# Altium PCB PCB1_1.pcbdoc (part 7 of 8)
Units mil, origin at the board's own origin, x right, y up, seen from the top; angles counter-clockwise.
Board outline 3937.01 x 3346.46 mil, 6 copper layers (Top Layer, Signal-1, SIG, POWER, Signal-4, Bottom Layer), stack 60.565 mil thick; 256 components, 201 nets, 1360 pads, 815 vias.
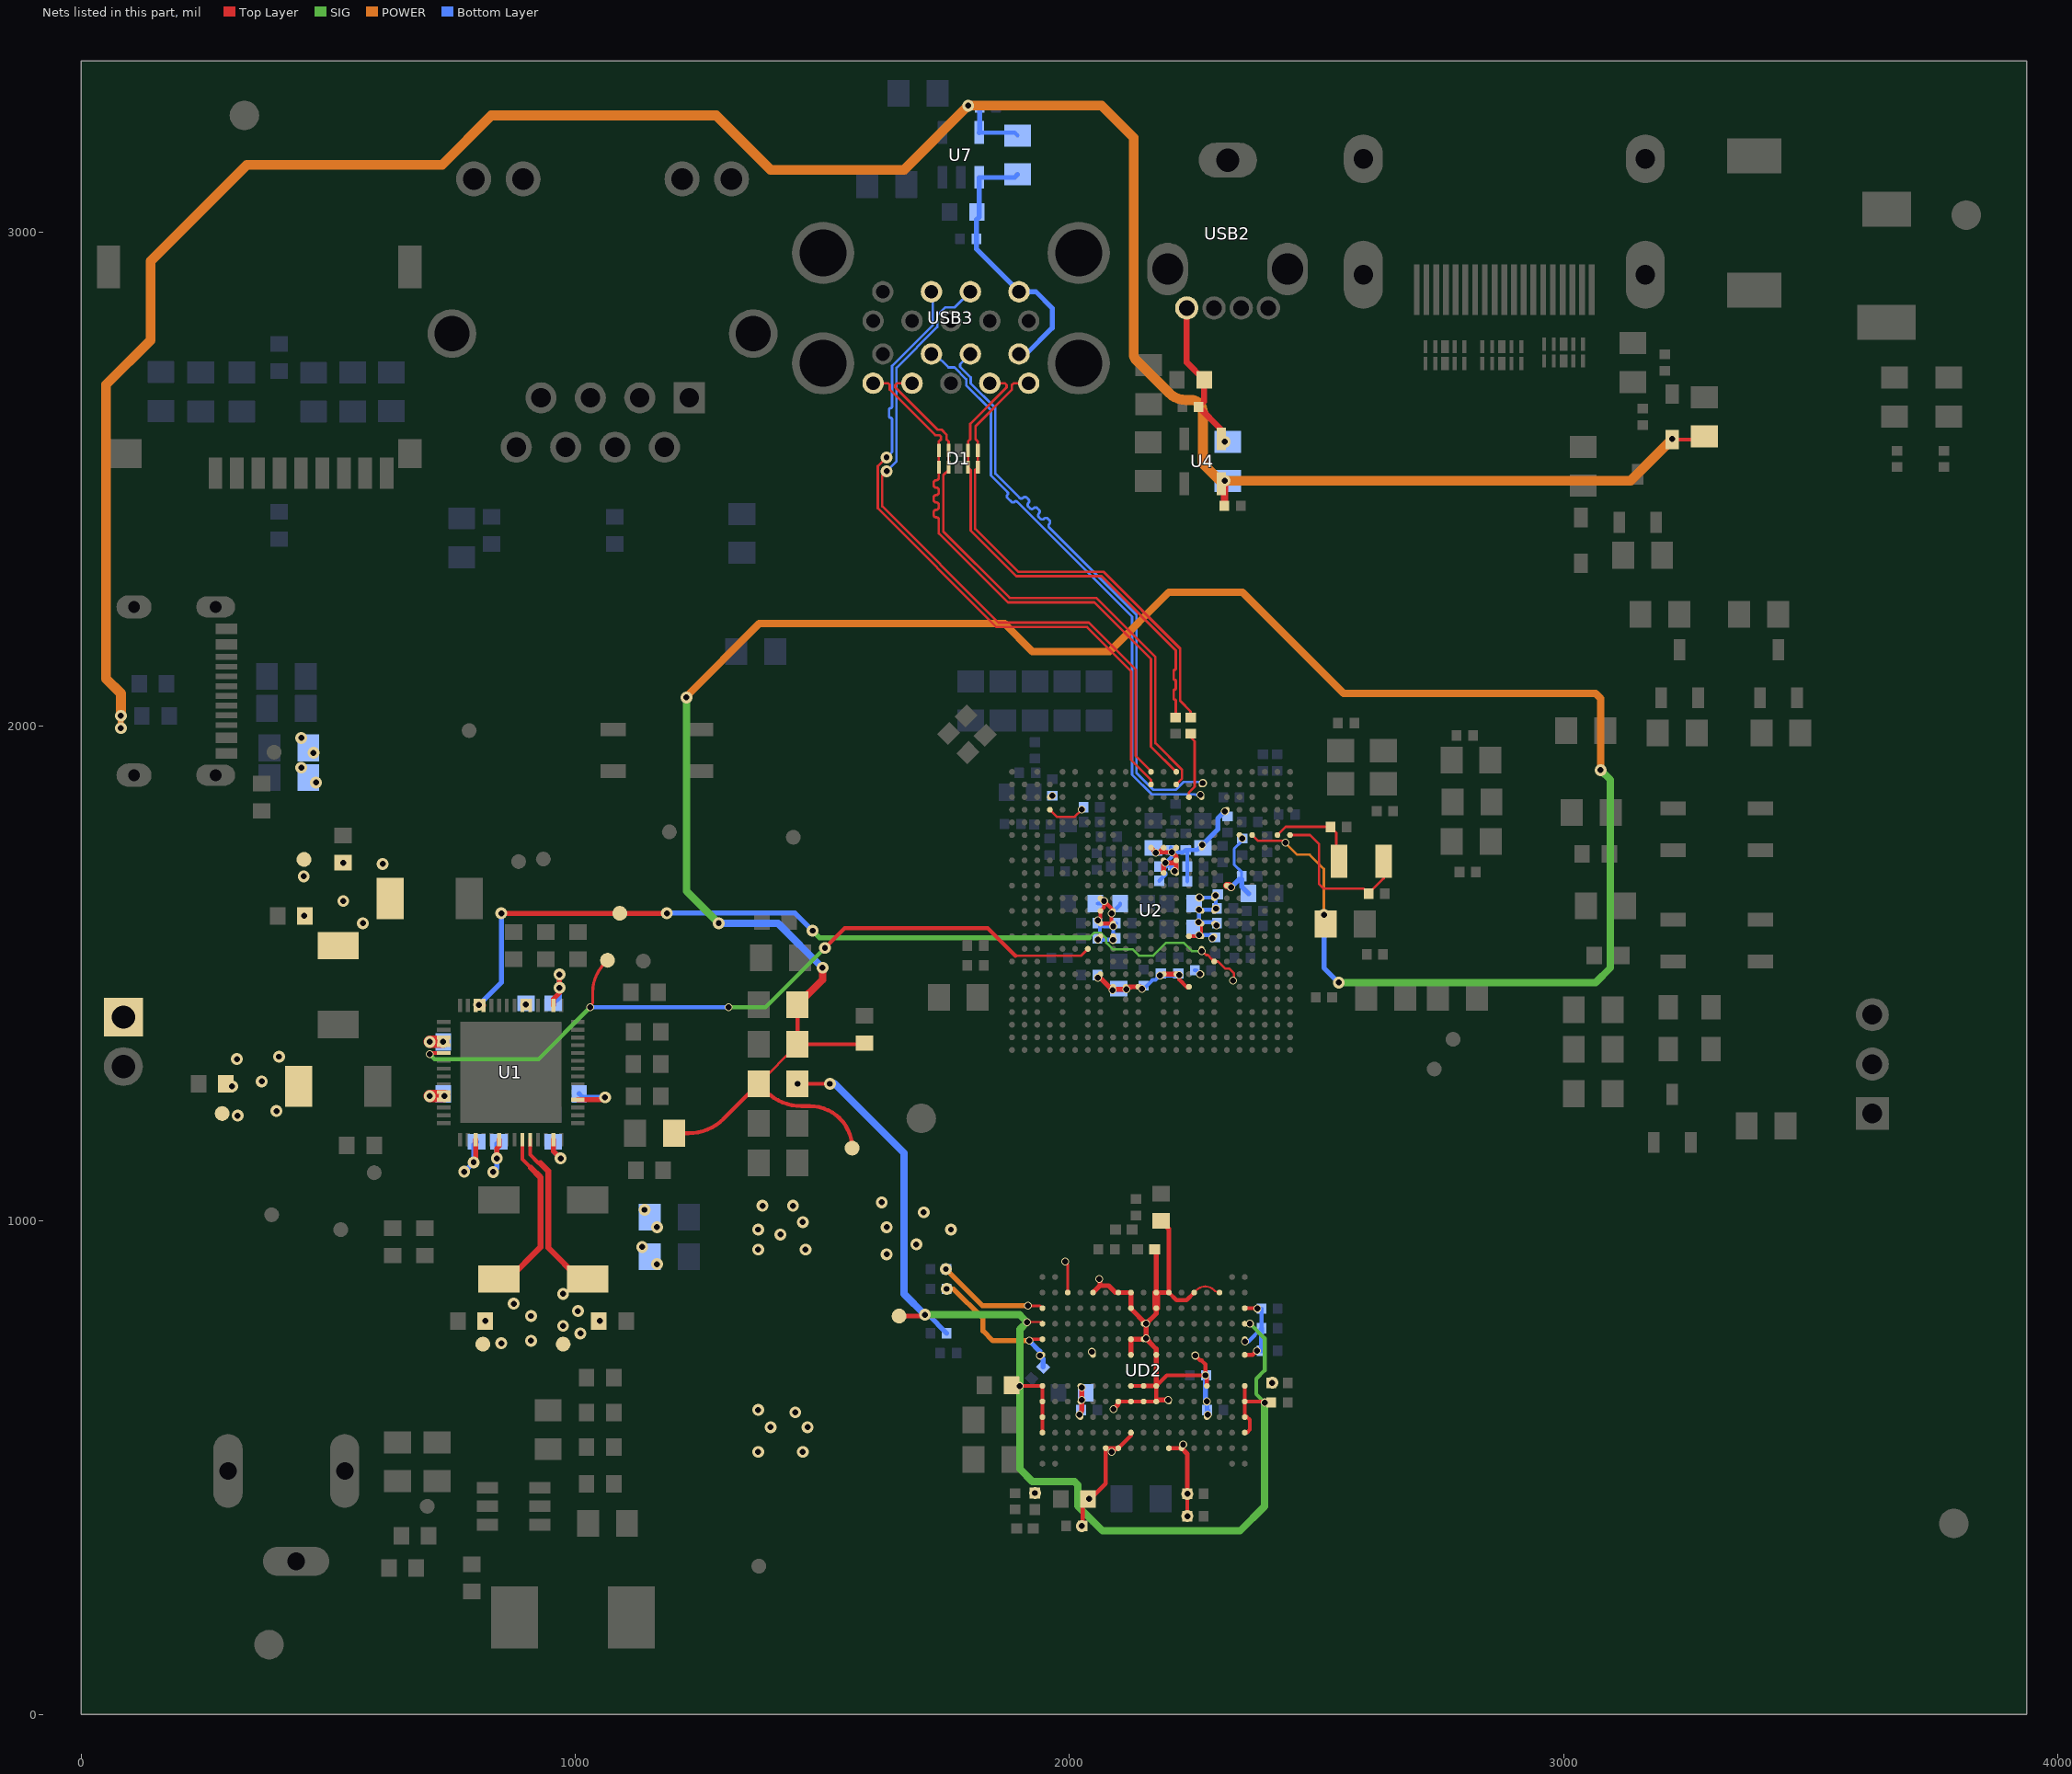
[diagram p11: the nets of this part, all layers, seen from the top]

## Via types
v1: diameter 16, hole 12, Top Layer to Bottom Layer, 426 vias
v2: diameter 24, hole 12, Top Layer to Bottom Layer, 385 vias
v3: diameter 34, hole 12, Top Layer to Bottom Layer, 2 vias
v4: diameter 30, hole 12, Top Layer to Bottom Layer, 2 vias

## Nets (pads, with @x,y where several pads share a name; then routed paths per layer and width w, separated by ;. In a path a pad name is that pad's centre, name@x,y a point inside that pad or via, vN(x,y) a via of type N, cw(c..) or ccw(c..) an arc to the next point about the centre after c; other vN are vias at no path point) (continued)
USB1-AP-SSTXP: C22.1 U2.C15 | length 136.3
  Top Layer w5: U2.C15@2241.77,1856.77 2241.77,1866.23 2253.18,1877.64 2253.18,1969.67 2245,1977.85 C22.1@2245,1984.92
USB1-DM: U2.B16 USB3.11 | length 1195.9
  Bottom Layer w5: USB3.11@1799.37,2753.62 1778.57,2732.83 1778.57,2727.83 1800,2706.4 1800,2694.2 1850,2644.2 1850,2511.46 1898.71,2462.75 ccw(c1902.46,2466.5) 1906.21,2462.75 cw(c1909.96,2459) 1913.71,2462.75 1916.82,2459.64 cw(c1913.07,2455.89) 1916.82,2452.14 ccw(c1920.57,2448.39) 1916.82,2444.64 1919.92,2441.53 ccw(c1923.67,2445.28) 1927.42,2441.54 cw(c1931.17,2437.78) 1934.92,2441.53 1938.03,2438.43 cw(c1934.28,2434.68) 1938.03,2430.93 ccw(c1941.78,2427.18) 1938.03,2423.43 1941.13,2420.32 ccw(c1944.88,2424.07) 1948.63,2420.32 cw(c1952.38,2416.57) 1956.13,2420.32 1959.24,2417.22 cw(c1955.49,2413.47) 1959.24,2409.72 ccw(c1962.99,2405.97) 1959.24,2402.22 2135.6,2225.86 2135.6,1905.86 2170,1871.46 2215,1871.46 2231.09,1887.55 v1@2270,1887.55
  other v1: 2270,1885.15
USB1-DP: U2.C16 USB3.12 | length 1195.9
  Bottom Layer w5: USB3.12@1720.63,2753.62 1727.83,2753.63 1755,2726.46 1767.22,2726.46 1791,2702.67 1791,2690.46 1841,2640.46 1841,2507.73 1874.25,2474.48 cw(c1871.27,2471.5) 1874.25,2468.52 ccw(c1877.23,2465.54) 1874.25,2462.56 1882.43,2454.37 ccw(c1885.41,2457.35) 1888.39,2454.37 cw(c1891.37,2451.39) 1894.35,2454.37 2126.6,2222.13 2126.6,1902.13 2166.27,1862.46 2254,1862.46 2255,1861.46 v1(2265,1861.46)
USB1-SSRXN: D1.1 D1.10 U2.A14 USB3.14 | length 1205.9
  Top Layer w5: USB3.14@1602.52,2694.57 1632.85,2694.57 1636.39,2691.03 1636.39,2681.47 1728.4,2589.47 1736.44,2589.47 1739.98,2585.93 1739.98,2580.93 1735.63,2576.59 D1.10@1735.63,2558.5 D1.1@1735.63,2524.42 1735.63,2503.49 cw(c1730.31,2503.49) 1730.31,2498.17 ccw(c1730.31,2492.86) 1725,2492.86 1725,2488.49 ccw(c1730.31,2488.49) 1730.31,2483.17 cw(c1730.31,2477.86) 1735.63,2477.86 1735.63,2473.49 cw(c1730.31,2473.49) 1730.31,2468.17 ccw(c1730.31,2462.86) 1725,2462.86 1725,2458.49 ccw(c1730.31,2458.49) 1730.31,2453.17 cw(c1730.31,2447.86) 1735.63,2447.86 1735.63,2443.49 cw(c1730.31,2443.49) 1730.31,2438.17 ccw(c1730.31,2432.86) 1725,2432.86 1725,2428.49 ccw(c1730.31,2428.49) 1730.31,2423.17 cw(c1730.31,2417.86) 1735.63,2417.86 1735.63,2390.67 1875.33,2250.97 2050.49,2250.97 2165,2136.46 2165,1959.13 U2.A14@2216.18,1907.95
USB1-SSRXP: D1.2 D1.9 U2.B14 USB3.15 | length 1205.2
  Top Layer w5: USB3.15@1681.26,2694.57 1650.93,2694.57 1647.39,2691.03 1647.39,2686.03 1732.95,2600.47 1741,2600.47 1750.98,2590.49 1750.98,2580.93 1755.32,2576.59 D1.9@1755.32,2558.5 D1.2@1755.32,2524.42 1755.32,2519.3 1744.63,2508.61 1744.63,2394.4 1879.05,2259.97 2054.21,2259.97 2174,2140.18 2174,1966.26 2227.59,1912.68 2227.59,1893.77 U2.B14@2216.18,1882.36
USB1-SSTXN: C23.2 D1.4 D1.7 USB3.17 | length 1024.9
  Top Layer w5: USB3.17@1838.74,2694.57 1869.07,2694.57 1872.61,2691.03 1872.61,2686.03 1799.03,2612.45 1799.03,2580.93 1794.69,2576.59 D1.7@1794.69,2558.5 D1.4@1794.69,2524.42 1800,2519.11 1800,2396.31 1892.42,2303.9 2064.83,2303.9 2215,2153.73 2215,2116.28 cw(c2213,2116.28) 2213,2114.28 ccw(c2213,2112.28) 2211,2112.28 2211,2096.28 ccw(c2213,2096.28) 2213,2094.28 cw(c2213,2092.28) 2215,2092.28 2215,2076.28 cw(c2213,2076.28) 2213,2074.28 ccw(c2213,2072.28) 2211,2072.28 2211,2056.28 ccw(c2213,2056.28) 2213,2054.28 cw(c2213,2052.28) 2215,2052.28 C23.2@2215,2018
USB1-SSTXP: C22.2 D1.5 D1.6 USB3.18 | length 1024.5
  Top Layer w5: USB3.18@1917.48,2694.57 1887.15,2694.57 1883.61,2691.03 1883.61,2681.47 1810.03,2607.89 1810.03,2580.93 1814.37,2576.59 D1.6@1814.37,2558.5 D1.5@1814.37,2524.42 1809,2519.05 1809,2400.04 1896.14,2312.9 2068.56,2312.9 2224,2157.46 2224,2051.46 2245,2030.46 C22.2@2245,2018
USB3-DM: U2.A12 USB3.2 | length 1389.4
  Top Layer w5: v2(1630,2516.46) 1621,2507.46 1621,2445.27 1856.3,2209.97 2039.21,2209.97 2134,2115.18 2134,1940.46 2165,1909.46 U2.A12@2165,1907.95
  Bottom Layer w5: v2(1630,2516.46) 1650,2536.46 1650,2725.85 1732.35,2808.19 1732.35,2832.01 1748.55,2848.21 1767.97,2848.21 USB3.2@1799.37,2879.61
USB3-DP: U2.B12 USB3.3 | length 1387.5
  Top Layer w5: v2(1629.77,2544.46) 1612,2526.68 1612,2441.55 1852.58,2200.97 2035.49,2200.97 2125,2111.46 2125,1931.82 2165,1891.82 U2.B12@2165,1882.36
  Bottom Layer w5: v2(1629.77,2544.46) 1641,2555.68 1641,2621.36 ccw(c1638,2621.36) 1638,2624.36 cw(c1638,2627.36) 1635,2627.36 1635,2641.36 cw(c1638,2641.36) 1638,2644.36 ccw(c1638,2647.36) 1641,2647.36 1641,2729.58 1723.35,2811.92 1723.35,2876.89 USB3.3@1720.63,2879.61
USB-5V: C4.2 C5.2 C7.2 C9.2 C12.2 C19.2 C27.2 C28.2 C124.2 C127.2 D5.1 H2.1 R19.1 R32.1 R35.1 R39.2 R40.2 R41.1 R42.1 U1.3 U1.6 U1.13 U1.18 U1.30 U1.33 U1.34 U1.45 U1.46 U1.52 U1.53 U4.5 U7.5 | length 5849.2
  Top Layer w8: D5.1@3220,2580.3 3278.21,2580.3 R19.1@3285,2587.09
  Top Layer w10: v2(793.96,1117.5) 798.15,1121.69 U1.3@798.15,1163.51 ; v2(840.96,1125.41) 840.96,1145.78 845.4,1150.23 U1.6@845.4,1163.51 ; U1.13@955.63,1163.51 955.63,1139.95 v2(970,1125.59) ; U1.30@955.63,1435.16 955.63,1448.44 967.83,1460.63 v2(967.83,1497.73) ; U1.18@1004.84,1244.22 1055.25,1244.22 v2(1060,1248.97)
  Top Layer w15: U4.5@2307.4,2491.04 2313.46,2484.98 C124.2@2313.46,2446.46
  Top Layer w25: v2(705,1251.46) v2(735,1251.46) ; v2(705,1361.46) v2(732.44,1361.46)
  POWER w12: v2(80,1996.46) v2(80,2021.46)
  POWER w20: v2(80,2021.46) 80,2066.46 50,2096.46 50,2691.46 140,2781.46 140,2941.46 335,3136.46 730,3136.46 830,3236.46 1285,3236.46 1395,3126.46 1665,3126.46 v2(1795,3256.46) 2065,3256.46 2130,3191.46 2130,2753.53 ccw(c2147.07,2753.53) 2135,2741.46 2202.19,2674.27 ccw(c2235.19,2707.27) 2235.19,2660.6 2245.86,2660.6 cw(c2245.86,2636.46) 2262.93,2653.53 cw(c2245.86,2636.46) 2270,2636.46 2270,2531.46 2304.37,2497.09 v2(2314.29,2497.09) 3135.63,2497.09 v2(3220,2581.46)
  Bottom Layer w8: U7.5@1817.4,3201.88 1888.95,3201.88 R35.1@1895,3195.83
  Bottom Layer w10: v2@774.99,1098.53 v2(793.96,1117.5) 793.96,1152.86 C28.2@800,1158.9 ; v2(833.48,1097.97) 840.96,1105.45 v2(840.96,1125.41) 840.96,1154.85 C9.2@845,1158.9 ; C7.2@955,1158.9 955,1140.59 v2(970,1125.59) ; C19.2@955,1439.02 967.83,1451.84 v2(967.83,1470.74) v2(967.83,1497.73) ; C5.2@1007.56,1256.46 1015.05,1248.97 v2(1060,1248.97) ; U7.5@1817.4,3201.88 1818.21,3202.69 C127.2@1818.21,3252.8
  Bottom Layer w12: v2(1795,3256.46) 1814.56,3256.46 C127.2@1818.21,3252.8
  other v2: 1165,911.46 1135,946.46 1165,986.46 1140,1021.46 774.93,1098.53 900,1437.05 475,1886.46 445,1916.46 470,1946.46 445,1976.46
USB-VBUS1: C125.1 C126.2 R32.2 U4.1 USB2.1 | length 303.1
  Top Layer w12: USB2.1@2237.4,2846.86 2237.4,2736.62 C125.1@2272.56,2701.46 2272.56,2657.48 C126.2@2261.54,2646.46 2307.4,2600.6 U4.1@2307.4,2581.88
  other v2: 2314.29,2575.83
USB-VBUS2: C128.1 C129.2 R35.2 U7.1 USB3.1 USB3.10 | length 559.7
  Bottom Layer w10: R35.2@1895,3117.09 1888.95,3111.04 U7.1@1817.4,3111.04 1817.4,3031.3 1812.56,3026.46 1811.54,3025.44 C129.2@1811.54,2986.46 1811.54,2966.46 1897.79,2880.21 USB3.1@1897.8,2879.61 1931.85,2879.61 1965,2846.46 1965,2806.46 1912.17,2753.63 USB3.10@1897.8,2753.62
VCC18-LPDDR3: C109.2 C110.2 C122.2 pad.1@1655,806.46 R6.2 UD2.A3 UD2.A4 UD2.A5 UD2.A6 UD2.A10 UD2.U3 UD2.U4 UD2.U5 UD2.U6 UD2.U10 | length 2590.7
  Top Layer w3.5: v1(1914.14,793.94) 1921.62,793.94 1921.78,794.1 1942.12,794.1 UD2.A10@1945.28,790.94
  Top Layer w4: UD2.U10@2354.72,790.94 2364.49,790.94 v1(2365,791.46)
  Top Layer w8: v1(1449.37,1276.46) v2(1515,1276.46) ; C122.2@1882.56,666.46 ccw(c1886.17,670.07) 1886.17,664.96 v1(1899.46,664.96) UD2.A6@1945.28,664.96 UD2.A5@1945.28,633.46 UD2.A4@1945.28,601.97 UD2.A3@1945.28,570.47 ; UD2.U3@2354.72,570.47 2359.02,570.47 2365,576.46 2365,596.46 2359.49,601.97 UD2.U4@2354.72,601.97 UD2.U5@2354.72,633.46 ; UD2.U6@2354.72,664.96 UD2.U5@2354.72,633.46 ; C109.2@2408.46,631.46 2406.45,633.46 UD2.U5@2354.72,633.46
  Top Layer w10: pad.1@1655,806.46 1701.52,806.46 ccw(c1701.52,814.94) v2(1707.52,808.94)
  SIG w8: v1(2365,791.46) 2395,761.46 2395,696.46 2377.99,679.45 2377.99,648.47 v1(2395,631.46)
  SIG w15: v2(1707.52,808.94) 1899.14,808.94 v1(1914.14,793.94) 1899.46,779.26 v1(1899.46,664.96) 1899.46,496.99 1925,471.46 2010,471.46 2017,464.46 2017,421.75 2047.76,390.98 2047.76,390.88 2067.18,371.46 2345,371.46 2395,421.46 v1(2395,631.46)
  Bottom Layer w10: v2(1707.52,808.94) 1714.06,808.94 C110.2@1751.54,771.46
  Bottom Layer w15: v2@1525,1276.46 1665,1136.46 1665,851.46 v2(1707.52,808.94)
VCC18-RTC: C16.2 pad.1@1560,1146.46 R4.1 R5.1 R6.1 R11.1 R56.1 U2.F20 | length 5222.9
  Top Layer w5: R6.1@1370.63,1276.46 R4.1@1449.37,1355.2 ; U2.F20@2369.72,1780 2381.13,1768.59 2432.58,1768.59 v1(2436.82,1764.35)
  Top Layer w8: R56.1@1199.37,1176.46 1229.21,1176.46 ccw(c1229.21,1276.46) 1299.92,1205.75 R6.1@1370.63,1276.46 1386.34,1260.75 ccw(c1457.05,1331.46) 1457.05,1231.46 1474.29,1231.46 cw(c1474.29,1145.24) 1535.25,1206.21 cw(c1475.5,1146.46) pad.1@1560,1146.46 ; R5.1@1449.37,1436.46 R4.1@1449.37,1356.46 1579.11,1356.46 ccw(c1579.11,1364.79) C16.2@1585,1358.9
  Top Layer w15: R5.1@1449.37,1436.46 1500,1487.09 v2(1500,1511.46)
  SIG w15: v2@1224.54,2060.46 1225,2060 1225,1666.46 v2(1290,1601.46) ; v2(2545,1481.46) 3065,1481.46 3095,1511.46 3095,1891.46 v2(3075,1911.46)
  POWER w5: v1(2436.82,1764.35) 2460.87,1740.3 2486.16,1740.3 2515,1711.46 v2(2515,1618.46)
  POWER w15: v2@1224.54,2060.46 1371.94,2207.86 1868.6,2207.86 1925,2151.46 2080.85,2151.46 2200.85,2271.46 2350,2271.46 2555,2066.46 3065,2066.46 3075,2056.46 v2(3075,1911.46)
  Bottom Layer w10: v2(2515,1618.46) 2515,1511.46 v2(2545,1481.46)
  Bottom Layer w15: v2(1290,1601.46) 1410,1601.46 v2(1500,1511.46)
  other v2: 1224.54,2058.46
VCC-DRAM: C8.2 C93.2 C94.2 C95.2 C96.2 C97.2 C98.2 C99.2 C100.2 C101.2 C102.2 C103.2 C104.2 C105.2 C106.2 C107.2 C115.2 C116.2 C117.2 C118.2 C119.2 C120.2 C121.2 L7.1 pad.1@975,749.58 R22.2 R68.2 U1.10 U2.U8 U2.U13 U2.U14 U2.U16 U2.V9 U2.V10 U2.V11 U2.V15 UD2.A8 UD2.A9 UD2.A11 UD2.C12 UD2.D4 UD2.D5 UD2.D6 UD2.E8 UD2.E12 UD2.F2 UD2.G2 UD2.G5 UD2.G12 UD2.H3 UD2.H5 UD2.H6 UD2.H8 UD2.H9 UD2.H11 UD2.H12 UD2.J5 UD2.J6 UD2.J9 UD2.J10 UD2.K5 UD2.K6 UD2.K8 UD2.K11 UD2.K12 UD2.L2 UD2.L5 UD2.L12 UD2.M2 UD2.N8 UD2.N12 UD2.P4 UD2.P5 UD2.P6 UD2.R12 UD2.U8 UD2.U9 UD2.U11 | length 3270.5
  Top Layer w4: UD2.N12@2252.36,853.94 2257.77,859.34 cw(c2274.94,842.17) 2274.94,866.46 cw(c2274.94,842.17) 2292.11,859.34 2293.26,858.2 ccw(c2303.54,868.48) UD2.R12@2303.54,853.94
  Top Layer w5: v1(1916,827.11) 1940.61,827.11 UD2.A11@1945.28,822.44 ; v1(1991.27,916.46) 1996.46,911.27 UD2.C12@1996.46,853.94
  Top Layer w6: v1(1918.68,756.54) 1921.59,759.45 UD2.A9@1945.28,759.45
  Top Layer w8: U1.10@908.39,1163.51 908.39,1133.06 925.69,1115.76 929.09,1115.76 ; C115.2@2026.54,381.46 2026.54,420.44 2073.23,467.12 UD2.F2@2073.23,538.98 UD2.G2@2098.82,538.98 2124.41,564.57 UD2.H3@2124.41,570.47 ; UD2.G5@2098.82,633.46 UD2.H5@2124.41,633.46 UD2.J5@2150,633.46 UD2.K5@2175.59,633.46 UD2.K6@2175.59,664.96 2197.09,686.46 v1(2275,686.46) ; UD2.H6@2124.41,664.96 UD2.J6@2150,664.96 ; UD2.L2@2201.18,538.98 UD2.M2@2226.77,538.98 ; UD2.L12@2201.18,853.94 2216.68,838.44 2236.87,838.44 UD2.N12@2252.36,853.94 ; v1(2222.3,1496.61) 2222.3,1487.14 U2.V15@2238.6,1470.84 ; v2(2238.46,401.46) v2(2238.46,446.46) ; v1(2255,726.46) 2265.03,716.43 2267.45,716.43 2275,708.88 v1(2275,686.46) ; UD2.P6@2277.95,664.96 2277.95,683.5 v1(2275,686.46) ; UD2.U8@2354.72,727.95 2370.83,727.95 v1(2379.33,736.46) ; UD2.U11@2354.72,822.44 2379.52,822.44 v1(2380.5,821.46)
  Top Layer w10: v1(2020,606.46) ccw(c2007.93,618.53) 2025,618.53 v1(2025,636.46) v1(2025,661.46) ; UD2.E12@2047.64,853.94 2061.54,867.84 ; v1(2057.64,1491.43) cw(c2057.64,1482.07) 2064.26,1488.69 v1(2087.26,1465.69) cw(c2092.98,1459.97) 2092.98,1468.06 v1(2114.94,1468.06) cw(c2126.65,1456.35) 2126.65,1472.91 U2.V11@2139.41,1472.91 cw(c2139.41,1465.3) 2144.79,1470.68 v1(2147.03,1468.45) ; v1(2060,881.46) 2061.54,879.91 2061.54,867.84 ; v1(2085,531.46) 2088.07,534.52 cw(c2098.82,523.77) UD2.G2@2098.82,538.98 ; v1(2089.06,618.08) 2094.84,623.86 ccw(c2085.23,633.46) UD2.G5@2098.82,633.46 ; UD2.H8@2124.41,727.95 UD2.H9@2124.41,759.45 2152.99,759.45 v1(2155,761.46) ; UD2.J6@2150,664.96 UD2.K6@2175.59,664.96 UD2.K8@2175.59,727.95 2175.59,739.78 2161.69,753.69 2161.69,754.77 v1(2155,761.46) ; R22.2@2172.04,941.46 2175.59,937.91 UD2.K12@2175.59,853.94 UD2.L12@2201.18,853.94 2201.18,982.72 C93.2@2185,998.9 ; UD2.K5@2175.59,633.46 cw(c2182.81,626.24) 2182.81,636.46 v1(2200,636.46) ; UD2.K11@2175.59,822.44 2175.59,811.54 UD2.J10@2155,790.94 ; U2.U13@2190.59,1498.5 2217.72,1498.5 cw(c2217.72,1492.04) v1(2222.3,1496.61) ; v1(2230,546.46) cw(c2219.74,546.46) 2226.99,539.2 UD2.M2@2226.77,538.98 2238.46,527.29 v2(2238.46,446.46) ; 2061.54,867.84 2078.99,867.84 2092.89,853.94 UD2.G12@2098.82,853.94 UD2.H12@2124.41,853.94 UD2.H11@2124.41,822.44 2124.41,821.54 UD2.J10@2155,790.94 ; v1(2155,761.46) UD2.J10@2155,790.94
  Top Layer w12: 929.09,1115.76 945,1099.85 945,944.65 1008.03,881.62 L7.1@1025,881.62
  Top Layer w15: UD2.K11@2175.59,822.44 UD2.K12@2175.59,853.94
  POWER w10: v2(1749.76,901.46) 1824.11,827.11 v1(1916,827.11) ; v2(1751.54,861.46) 1765,861.46 1825,801.46 1825,776.46 1844.92,756.54 v1(1918.68,756.54)
  Bottom Layer w8: v1(2087.26,1465.69) C117.2@2112.57,1465.69 ; C116.2@2146.64,1468.06 v1(2147.03,1468.45) ; C116.2@2150.18,1468.45 2168.41,1486.68 2174.24,1486.68 v1(2183.42,1495.86) 2215.94,1495.86 C121.2@2220,1499.92 ; C120.2@2253.46,1506.46 2256.4,1506.46 v1(2264.4,1498.46) ; v1(2355,754.96) 2361.96,754.96 C96.2@2388.46,781.46 C97.2@2388.46,821.46
  Bottom Layer w10: v1(1918.68,756.54) 1940,735.21 v1(1940,726.46) ; C103.2@1946.7,703.15 1946.7,719.76 ; v1(2020,606.46) ccw(c2007.93,618.53) 2025,618.53 v1(2025,636.46) v1(2025,661.46) ; v1(2275,686.46) 2275,636.42 v1(2277.95,633.46) 2278.46,632.96 C101.2@2278.46,616.46 2280,614.92 v1(2280,606.46) ; C94.2@2388.46,736.46 C96.2@2388.46,781.46
  other v1: 2045.47,733.88 2155,791.46
  other v2: 2024.76,381.46 2040,436.46 1930,448.2 1370,531.46 1460,531.46 1395,581.46 1470,581.46 1445,611.46 1370,616.46 2410.24,671.46 1010,771.46 975,786.46 1049.41,796.46 1005,816.46 975,851.46
VDD-CPU: C10.2 C15.2 C60.2 C61.2 C62.2 C68.2 C69.2 C70.2 L9.1 L10.1 pad.4@450.59,1730.64 U2.L16 U2.L17 U2.M16 U2.M17 U2.N16 U2.N17 U2.P15 U2.P16 U2.P17 | length 242.8
  Top Layer w5: v1(2261.53,1603.5) 2267.36,1597.67 U2.P16@2267.36,1575.28
  Top Layer w8: U2.P15@2241.77,1575.28 2257.03,1575.28 ccw(c2257.03,1583.02) v1(2262.5,1577.54)
  Bottom Layer w8: v1(2262.5,1577.54) 2283.2,1577.54 v1(2289.31,1571.43) ; C61.2@2262.5,1602.53 v1(2261.53,1603.5) ; v1(2262.66,1653.52) 2291.24,1653.52 v1(2295.26,1657.54) 2296.17,1656.63 v1(2296.17,1631.11) 2293.83,1628.77 v1(2262.19,1628.77) 2262.19,1604.15 v1(2261.53,1603.5) ; v1(2297.54,1597.39) 2291.43,1603.5 v1(2261.53,1603.5)
  other v2: 570,1601.46 450.59,1616.46 530,1646.46 450,1696.46 610,1721.46 530,1723.9
VDD-CPUFB: pad.1@1089.86,1621.46 U1.39 U1.40 U2.R16 U2.T17 | length 2131.6
  Top Layer w5: v1(2268.1,1545.28) 2276.42,1536.96 2279.87,1536.96 2288.07,1528.76 2288.29,1528.76 U2.T17@2292.95,1524.09 2300.81,1524.09 2315,1509.91 2323.27,1509.91 2332.73,1500.45 2332.73,1487.37 v1(2330.91,1485.55)
  Top Layer w10: v2(805,1436.46) 812.6,1436.46 U1.39@813.9,1435.16 ; v2(850,1621.46) v2(1185,1621.46) pad.1@1089.86,1621.46 v2(850,1621.46)
  SIG w5: 2039.98,1572.34 2049.66,1582.01 2063.21,1582.01 2074.42,1570.79 2074.42,1562 2087.55,1548.87 2127.59,1548.87 2140.49,1535.97 2169.51,1535.97 2195.41,1561.86 2230.93,1561.86 2247.51,1545.28 v1(2268.1,1545.28)
  SIG w10: v2(1480,1586.46) 1494.12,1572.34 2039.98,1572.34
  Bottom Layer w10: v2(805,1436.46) 850,1481.46 v2(850,1621.46) ; v2(1185,1621.46) 1185.5,1621.96 1444.5,1621.96 v2(1480,1586.46)
VDD-CPUS: C48.2 C49.2 C50.2 U2.F19 U2.K18 | length 172.1
  Top Layer w10: U2.F19@2344.13,1780 2349.63,1774.5 v1(2349.63,1773)
  Top Layer w15: U2.K18@2318.54,1677.64 2323.42,1677.64 v1(2326.88,1674.18)
  Bottom Layer w6: C50.2@2348.46,1696.46 2348.46,1704.94 2333.37,1720.03 2333.37,1752.24 2349.63,1768.5 C49.2@2349.63,1771.83
  Bottom Layer w8: C49.2@2349.63,1771.83 v1(2349.63,1773)
  Bottom Layer w10: v1(2326.88,1674.18) 2343.46,1690.76 2348.46,1690.76 2348.46,1675.44 C48.2@2362.44,1661.46
VDD-GPU: C21.2 C71.2 C72.2 C73.2 C74.2 C75.2 C76.2 L1.1 pad.3@285,1216.46 U2.L8 U2.M8 U2.M9 U2.N8 U2.N9 U2.P8 U2.P9 | length 306.3
  Top Layer w8: v1(2057.19,1607.1) 2062.64,1612.55 U2.M8@2062.64,1626.46 2070,1633.82 v1(2070,1646.46) ; U2.N8@2062.64,1600.87 2082.6,1600.87 U2.N9@2085,1598.47 ; U2.L8@2062.64,1652.05 2064.41,1652.05 v1(2070,1646.46) ; v1(2085,1621.46) U2.N9@2085,1598.47 ; U2.M9@2088.23,1626.46 2088.23,1628.23 v1(2070,1646.46) ; v1(2088.53,1594.93) U2.N9@2085,1598.47
  Bottom Layer w8: v1(2057.19,1607.1) 2069.36,1594.93 v1(2088.53,1594.93) ; C71.2@2057.56,1641.46 C71.2@2065,1641.46 ; C73.2@2061.54,1601.46 2061.54,1572.14 v1(2057.41,1568.01) 2088.21,1568.01 v1(2088.42,1567.8) 2088.53,1567.9 v1(2088.53,1594.93) ; v1(2085,1621.46) 2102.44,1638.9 C72.2@2102.44,1641.46 ; C75.2@2093.46,1601.46 2093.46,1599.86 v1(2088.53,1594.93)
  other v2: 1630,931.46 1370,940.91 1465.75,940.91 1690,951.46 1415,971.46 1370,981.46 1760,981.46 1630,986.46 1460,996.46 1705,1016.46 1378.5,1029.64 1440.25,1029.64 1620,1036.46 316.15,1212.04 395,1221.46 305,1271.46 365,1281.46 315,1326.46 400,1331.46
VDD-GPUFB: pad.1@1065,1526.46 U1.47 U2.R7 | length 1609.1
  Top Layer w5: 1890.77,1535.69 2023.05,1535.69 U2.R7@2037.05,1549.69
  Top Layer w6: v1(1030,1431.46) ccw(c1017.93,1443.53) 1035,1443.53 1035,1461.46 cw(c1119.5,1461.46) 1059.75,1521.21 pad.1@1065,1526.46
  Top Layer w8: v1(705,1336.46) 707.25,1338.71 U1.47@733.19,1338.71 ; v2(1505,1551.46) 1545,1591.46 1834.39,1591.46 1890.16,1535.69 1890.77,1535.69
  SIG w8: v1(705,1336.46) 715,1326.46 925,1326.46 v1(1030,1431.46) ; v1(1310,1431.46) 1385,1431.46 v2(1505,1551.46)
  Bottom Layer w8: v1(1030,1431.46) v1(1310,1431.46)
VDD-SYS: C6.2 C32.2 C38.2 C45.2 C46.2 C77.2 C78.2 C79.2 C80.2 C81.2 C82.2 L8.1 pad.2@812.63,749.58 U1.9 U2.D18 U2.G12 U2.G13 U2.G14 U2.G16 U2.H13 U2.H14 U2.J13 U2.J14 | length 783.3
  Top Layer w8: U1.9@892.64,1163.51 892.64,1123.81 910,1106.46 ; v1@2181.13,1744.95 v1(2207.18,1744.95) 2216.18,1753.95 U2.G14@2216.18,1754.41 ; U2.H13@2189.83,1728.06 v1(2194.36,1723.54)
  Top Layer w10: U2.G12@2165,1754.41 2175,1744.41 v1(2175,1744.16) 2180.35,1744.16 2181.13,1744.95 U2.G13@2190.59,1754.41 ; U2.J13@2190.59,1703.23 v1@2190.59,1719.77 ; v1(2194.36,1723.54) 2210.9,1723.54 U2.H14@2216.18,1728.82 ; v1(2207.18,1744.95) 2216.18,1735.95 U2.H14@2216.18,1728.82 ; v1(2212.43,1706.76) 2216.18,1710.51 U2.H14@2216.18,1728.82
  Top Layer w12: L8.1@845,881.62 865.16,881.62 929,945.46 929,1087.46 910,1106.46
  Bottom Layer w8: C32.2@2181.69,1687.35 2194.36,1700.02 2194.36,1703.4 ; 2194.36,1714.86 v1@2198.7,1719.2 ; v1@2198.7,1727.87 2207.18,1736.35 ; C80.2@2205,1754.41 2205,1747.13 v1(2207.18,1744.95) 2230.04,1744.95 C45.2@2235,1749.92 ; C46.2@2206.5,1712.69 C46.2@2206.5,1719.07 ; C38.2@2238.46,1686.46 C79.2@2238.46,1716.46 2238.46,1746.46 C45.2@2235,1749.92 ; v1(2268.72,1760.18) 2258.46,1749.92 C45.2@2235,1749.92
  Bottom Layer w10: v1(2268.72,1760.18) 2300,1791.46 2300,1813.42 v1(2314.64,1828.07)
  other v2: 850,751.46 910,756.46 817.56,796.46 910,806.46 875,831.46
VRA1: C34.2 U2.C4
  other v1: 1965,1859.92
VRA2: C56.2 U2.D4 | length 76.6
  Top Layer w5: U2.D4@1960.28,1831.18 1974.46,1817 2010.63,1817 v1(2025,1831.37)
X32KIN: C88.1 U2.F23 X2.2 | length 333.3
  Top Layer w5: U2.F23@2446.5,1780 2487.07,1780 2505,1762.07 2505,1681.46 2515,1671.46 2595.61,1671.46 C88.1@2605.38,1661.69 2636.23,1692.53 X2.2@2636.23,1727.05
X32KOUT: C89.1 U2.F22 X2.1 | length 190.8
  Top Layer w5: U2.F22@2420.91,1780 2437.57,1796.66 C89.1@2528.06,1796.66 2540,1784.72 2540,1732.33 X2.1@2545.28,1727.05
pads on no net: CN1.14 DC1.3 SW1.2 SW1.3 SW2.2 SW2.3 SW3.2 SW3.3 U1.5 U1.14 U1.21 U1.22 U1.55 U1.56 U2.A8 U2.A9 U2.A10 U2.AA3 U2.AA10 U2.B1 U2.B2 U2.B8 U2.B9 U2.B10 U2.C1 U2.C2 U2.C23 U2.D9 U2.D11 U2.D15 U2.D16 U2.E12 U2.E17 U2.E21 U2.E22 U2.F5 U2.F8 U2.F9 U2.F11 U2.G10 U2.G20 U2.H2 U2.H3 U2.H4 U2.H5 U2.H17 U2.H19 U2.H21 U2.H22 U2.J2 U2.J3 U2.J5 U2.J6 U2.J19 U2.J20 U2.J22 U2.K1 U2.K2 U2.K3 U2.K22 U2.L2 U2.L3 U2.L4 U2.L5 U2.L6 U2.L19 U2.L20 U2.L21 U2.L22 U2.M2 U2.M3 U2.M4 U2.M5 U2.M6 U2.M21 U2.M22 U2.N2 U2.N3 U2.N20 U2.N22 U2.N23 U2.P1 U2.P2 U2.P3 U2.P4 U2.P5 U2.P6 U2.P21 U2.P22 U2.R2 U2.R3 U2.R5 U2.R19 U2.R20 U2.R21 U2.R22 U2.R23 U2.T1 U2.T2 U2.T3 U2.T20 U2.T21 U2.T22 U2.U2 U2.U3 U2.U4 U2.U5 U2.U19 U2.U21 U2.V1 U2.V2 U2.V3 U2.V21 U2.V22 U2.V23 U2.W4 U2.W11 U2.Y21 UD2.A1 UD2.A2 UD2.A12 UD2.A13 UD2.B1 UD2.B13 UD2.C4 UD2.K9 UD2.R3 UD2.T1 UD2.T13 UD2.U1 UD2.U2 UD2.U12 UD2.U13 USB3.5 USB3.6 USB3.8 USB3.9 USB4.A6 USB4.A7 USB4.A8 USB4.B6 USB4.B7 USB4.B8

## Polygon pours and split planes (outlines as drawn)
VCC-DRAM on POWER (solid, remove dead copper): 1320.63,676.11 1689.65,676.11 1715,701.46 1715,741.46 1725,751.46 1785,751.46 1810,776.46 1810,1526.46 1811.77,1524.69 2460,1524.69 2460,1461.91 2655,1266.91 2655,406.46 2600,351.46 1525,351.46 1505,371.46 1505,501.46 1500,496.46 1325,496.46 1320.63,500.83
DC-5V on Bottom Layer (solid, remove dead copper, pour order 24): 1190,727.18 1190,1046.46 1290,1046.46 1290,506.46 1055,506.46 1055,727.18
LXC on Top Layer (solid, remove dead copper, pour order 20): 565,1321.46 570,1316.46 675,1316.46 675,1226.46 564.49,1226.46 564.49,1320.95
LXE on Top Layer (solid, remove dead copper, pour order 18): 962.52,1104.07 1047.38,1104.07 1070,1081.46 1070,1011.46 1065,1006.46 970,1006.46 962.52,1013.93
VDD-GPU on Top Layer (solid, remove dead copper, pour order 16): 485,1191.46 265,1191.46 262.68,1193.77 262.68,1354.13 485,1354.13
DC-5V on Top Layer (solid, remove dead copper, pour order 0): 1050,728.11 1053.35,731.46 1290,731.46 1290,526.46 1266.45,502.9 1050,502.9
VCC-DRAM on Top Layer (solid, remove dead copper, pour order 14): 950,914.49 951.96,916.46 1075,916.46 1080,911.46 1080,746.46 1070,736.46 1040,736.46 1032.45,728.9 950,728.9
VDD-SYS on Top Layer (solid, remove dead copper, pour order 12): 790,916.46 925,916.46 930,911.46 930,746.46 912.53,728.99 790,728.99
LXD on Top Layer (solid, remove dead copper, pour order 10): 800,1076.46 846.29,1076.46 862.5,1092.67 878.79,1092.67 880,1091.46 889.2,1091.46 889.2,1007.69 801.23,1007.69 800,1006.46
LXB on Top Layer (solid, remove dead copper, pour order 6): 832.95,1484.41 792.05,1484.41 765,1511.46 765,1587.24 753.2,1599.03 753.2,1698.29 832.95,1698.29
LXA on Top Layer (solid, remove dead copper, pour order 4): 750.44,1382.01 579.26,1382.01 579.26,1376.46 570,1376.46 570,1366.17 475,1366.17 475,1426.46 745,1426.46 745,1406.46 750.44,1406.46
VDD-CPU on Top Layer (solid, remove dead copper, pour order 8): 426.93,1751.45 655,1751.45 665,1741.46 665,1593.07 598.39,1526.46 430,1526.46 425,1531.46 425,1749.53
TYPE-5V on Top Layer (solid, remove dead copper, pour order 2): 335,1991.46 410,1991.46 410,1866.26 335,1866.26
VDD-GPU on POWER (solid, remove dead copper): 255,1346.46 665,1346.46 665,1076.46 1106.84,1076.46 1106.84,889.61 1115,881.46 1195,881.46 1195,1131.46 1190,1136.46 1193.89,1140.35 1511.84,1140.35 1511.84,753.3 1490,731.46 945,731.46 945,747.68 935,757.68 935,906.46 915,926.46 275,926.46 255,946.46
USB-5V on POWER (solid, remove dead copper): 500,2036.46 500,1866.46 385,1866.46 385,1531.46 1189.49,1531.46 1189.49,882.65 1120,882.65 1120,1081.46 677.54,1081.46 677.54,1356.46 30,1356.46 30,2036.46
GND on SIG (solid, remove dead copper): -1300,3826.46 -1300,-983.54 5155,-983.54 5155,3826.46
GND on Bottom Layer (solid, remove dead copper, pour order 48): -545,3516.46 -545,-583.54 4490,-583.54 4490,3516.46
GND on POWER (solid, remove dead copper): -1580,4016.46 -1580,-1173.54 5765,-1173.54 5765,4016.46
GND on Top Layer (solid, remove dead copper, pour order 22): -395,3566.46 -395,-893.54 4765,-893.54 4765,3566.46
VDD-GPU on POWER (solid, remove dead copper): 1605,816.46 1585,836.46 1585,1677.64 1593.82,1686.46 2205,1686.46 2205,1526.46 1806.38,1526.46 1805,1525.07 1805,836.46 1785,816.46
VDD-SYS on POWER (solid, remove dead copper): 2227.27,1785.98 2227.27,1686.46 1845,1686.46 1840,1681.46 1595,1681.46 1595,773.3 1561.22,648.84 796.37,648.84 775,741.46 775,903.3 790,918.3 930,918.3 930,786.46 948.26,733.9 1508.19,733.9 1510,739.65 1510,1756.46 1539.52,1785.98
VDD-CPU on POWER (solid, remove dead copper): 2208.56,1524.09 2208.56,1791.39 752.86,1789.31 735,1771.46 735,1606.46 665,1536.46 410,1536.46 393.75,1552.71 393.75,1844.74 485.47,1936.46 2360,1936.46 2430,1866.46 2430,1526.46 2377.36,1526.46 2375,1524.09
VDD-GPU on SIG (solid, remove dead copper): 1315,1086.46 1779,1086.46 1801,1064.46 1801,892.57 1789.89,881.46 1315,881.46
VCC-DRAM on SIG (solid, remove dead copper): 951.96,881.46 1555.13,881.46 1555.13,446.46 1320.63,446.46 1320.63,733.88 951.96,733.88

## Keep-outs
Board Outline Layer:
  region: 738.07,3344.92 738.07,2494.53 1371.93,2494.53 1371.93,3344.92
  region: 228.43,3221.46 cw(c130,3221.46) 31.57,3221.46 cw(c130,3221.46)
  circle w0.1: c130,3221.46 r98.43
  region: 228.43,3221.46 228.03,3212.63 226.84,3203.88 224.88,3195.27 222.15,3186.87 218.68,3178.75 214.49,3170.97 209.63,3163.6 204.12,3156.7 198.02,3150.32 191.37,3144.5 184.22,3139.31 176.64,3134.78 168.68,3130.95 160.42,3127.85 151.9,3125.5 143.21,3123.92 134.42,3123.13 125.58,3123.13 116.79,3123.92 108.1,3125.5 99.58,3127.85 91.32,3130.95 83.36,3134.78 75.78,3139.31 68.63,3144.5 61.98,3150.32 55.88,3156.7 50.37,3163.6 45.51,3170.97 41.32,3178.75 37.85,3186.87 35.12,3195.27 33.16,3203.88 31.97,3212.63 31.57,3221.46 31.97,3230.28 33.16,3239.03 35.12,3247.64 37.85,3256.04 41.32,3264.16 45.51,3271.94 50.37,3279.31 55.88,3286.21 61.98,3292.6 68.63,3298.41 75.78,3303.6 83.36,3308.13 91.32,3311.96 99.58,3315.06 108.1,3317.41 116.79,3318.99 125.58,3319.78 134.42,3319.78 143.21,3318.99 151.9,3317.41 160.42,3315.06 168.68,3311.96 176.64,3308.13 184.22,3303.6 191.37,3298.41 198.02,3292.6 204.12,3286.21 209.63,3279.31 214.49,3271.94 218.68,3264.16 222.15,3256.04 224.88,3247.64 226.84,3239.03 228.03,3230.28
  region: 223.43,126.46 cw(c125,126.46) 26.57,126.46 cw(c125,126.46)
  circle w0.1: c125,126.46 r98.43
  region: 223.43,126.46 223.03,117.63 221.84,108.88 219.88,100.27 217.15,91.87 213.68,83.75 209.49,75.97 204.63,68.6 199.12,61.7 193.02,55.32 186.37,49.5 179.22,44.31 171.64,39.78 163.68,35.95 155.42,32.85 146.9,30.5 138.21,28.92 129.42,28.13 120.58,28.13 111.79,28.92 103.1,30.5 94.58,32.85 86.32,35.95 78.36,39.78 70.78,44.31 63.63,49.5 56.98,55.32 50.88,61.7 45.37,68.6 40.51,75.97 36.32,83.75 32.85,91.87 30.12,100.27 28.16,108.88 26.97,117.63 26.57,126.46 26.97,135.28 28.16,144.03 30.12,152.64 32.85,161.04 36.32,169.16 40.51,176.94 45.37,184.31 50.88,191.21 56.98,197.6 63.63,203.41 70.78,208.6 78.36,213.13 86.32,216.96 94.58,220.06 103.1,222.41 111.79,223.99 120.58,224.78 129.42,224.78 138.21,223.99 146.9,222.41 155.42,220.06 163.68,216.96 171.64,213.13 179.22,208.6 186.37,203.41 193.02,197.6 199.12,191.21 204.63,184.31 209.49,176.94 213.68,169.16 217.15,161.04 219.88,152.64 221.84,144.03 223.03,135.28
  region: 3908.43,126.46 cw(c3810,126.46) 3711.57,126.46 cw(c3810,126.46)
  circle w0.1: c3810,126.46 r98.43
  region: 3908.43,126.46 3908.03,117.63 3906.84,108.88 3904.88,100.27 3902.15,91.87 3898.68,83.75 3894.49,75.97 3889.63,68.6 3884.12,61.7 3878.02,55.32 3871.37,49.5 3864.22,44.31 3856.64,39.78 3848.68,35.95 3840.42,32.85 3831.9,30.5 3823.21,28.92 3814.42,28.13 3805.58,28.13 3796.79,28.92 3788.1,30.5 3779.58,32.85 3771.32,35.95 3763.36,39.78 3755.78,44.31 3748.63,49.5 3741.98,55.32 3735.88,61.7 3730.37,68.6 3725.51,75.97 3721.32,83.75 3717.85,91.87 3715.12,100.27 3713.16,108.88 3711.97,117.63 3711.57,126.46 3711.97,135.28 3713.16,144.03 3715.12,152.64 3717.85,161.04 3721.32,169.16 3725.51,176.94 3730.37,184.31 3735.88,191.21 3741.98,197.6 3748.63,203.41 3755.78,208.6 3763.36,213.13 3771.32,216.96 3779.58,220.06 3788.1,222.41 3796.79,223.99 3805.58,224.78 3814.42,224.78 3823.21,223.99 3831.9,222.41 3840.42,220.06 3848.68,216.96 3856.64,213.13 3864.22,208.6 3871.37,203.41 3878.02,197.6 3884.12,191.21 3889.63,184.31 3894.49,176.94 3898.68,169.16 3902.15,161.04 3904.88,152.64 3906.84,144.03 3908.03,135.28
  region: 3903.43,3221.46 cw(c3805,3221.46) 3706.57,3221.46 cw(c3805,3221.46)
  circle w0.1: c3805,3221.46 r98.43
  region: 3903.43,3221.46 3903.03,3212.63 3901.84,3203.88 3899.88,3195.27 3897.15,3186.87 3893.68,3178.75 3889.49,3170.97 3884.63,3163.6 3879.12,3156.7 3873.02,3150.32 3866.37,3144.5 3859.22,3139.31 3851.64,3134.78 3843.68,3130.95 3835.42,3127.85 3826.9,3125.5 3818.21,3123.92 3809.42,3123.13 3800.58,3123.13 3791.79,3123.92 3783.1,3125.5 3774.58,3127.85 3766.32,3130.95 3758.36,3134.78 3750.78,3139.31 3743.63,3144.5 3736.98,3150.32 3730.88,3156.7 3725.37,3163.6 3720.51,3170.97 3716.32,3178.75 3712.85,3186.87 3710.12,3195.27 3708.16,3203.88 3706.97,3212.63 3706.57,3221.46 3706.97,3230.28 3708.16,3239.03 3710.12,3247.64 3712.85,3256.04 3716.32,3264.16 3720.51,3271.94 3725.37,3279.31 3730.88,3286.21 3736.98,3292.6 3743.63,3298.41 3750.78,3303.6 3758.36,3308.13 3766.32,3311.96 3774.58,3315.06 3783.1,3317.41 3791.79,3318.99 3800.58,3319.78 3809.42,3319.78 3818.21,3318.99 3826.9,3317.41 3835.42,3315.06 3843.68,3311.96 3851.64,3308.13 3859.22,3303.6 3866.37,3298.41 3873.02,3292.6 3879.12,3286.21 3884.63,3279.31 3889.49,3271.94 3893.68,3264.16 3897.15,3256.04 3899.88,3247.64 3901.84,3239.03 3903.03,3230.28
  lines w10: 0,0 0,3346.46 3937.01,3346.46 3937.01,0 0,0

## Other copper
Top Layer:
  drawing of 1206 lines, arcs and shapes, not listed
Signal-1:
  drawing of 93 lines, arcs and shapes, not listed
SIG:
  region net $2N15: 1184.55,3070.97 1178.89,3076.63 1180.06,3078.09 1180.96,3079.81 1181.61,3081.75 1182.04,3083.88 1182.28,3086.16 1182.36,3088.55 1182.15,3093.5 1181.63,3098.44 1181.03,3103.06 1180.57,3107.06 1180.47,3110.13 1218.05,3072.55 1214.98,3072.65 1210.98,3073.11 1206.36,3073.71 1201.42,3074.23 1196.47,3074.44 1194.08,3074.36 1191.8,3074.12 1189.67,3073.69 1187.73,3073.04 1186.01,3072.14
  region net VCC18-LPDDR3: 2375.53,786.58 2369.87,780.93 2368.75,781.81 2367.31,782.61 2365.81,783.2 2364.5,783.47 2372.98,791.96 2373.26,790.65 2373.85,789.15 2374.65,787.71
  region net VCC18-LPDDR3: 1902.05,795.43 1912.66,806.03 1916.74,802.31 1919.8,799.6 1908.49,788.28 1905.78,791.35
  region net VCC18-LPDDR3: 1912.66,781.85 1902.05,792.46 1905.78,796.54 1908.49,799.6 1919.8,788.28 1916.74,785.58
  region net BLDO1: 2325,1566.08 2315,1564.02 2314.88,1565.77 2314.57,1567.46 2314.13,1568.83 2313.62,1569.62 2325.45,1571.68 2325.25,1570.95 2325.11,1569.61
  region net AP-NMI: 2400.64,1757.2 2404.17,1753.67 2403.72,1752.79 2403.28,1751.22 2402.91,1749.27 2402.69,1747.23 2394.2,1755.72 2396.24,1755.94 2398.19,1756.3 2399.76,1756.75
  region net CLDO2: 1123.69,1398.31 1134.3,1387.71 1132.54,1385.77 1130.99,1383.74 1129.88,1381.94 1129.42,1380.71 1116.69,1393.43 1117.93,1393.89 1119.72,1395.01 1121.76,1396.56
  region net BLDO2: 598.81,1168.31 609.42,1157.71 607.66,1155.77 606.11,1153.74 605,1151.94 604.54,1150.71 591.81,1163.43 593.05,1163.89 594.84,1165.01 596.88,1166.56
  region net BLDO2: 608.9,1155.46 608.9,1147.46 607.41,1147.03 605.25,1145.89 602.81,1144.29 600.5,1142.46 600.5,1160.46 602.81,1158.62 605.25,1157.02 607.41,1155.89
  region net BLDO1: 646.34,987.05 646.34,977.05 644.53,976.7 642.26,975.8 639.93,974.52 637.94,973.05 637.94,991.05 639.93,989.58 642.26,988.3 644.53,987.39
  region net CLDO1: 1111.91,1332.05 1126.91,1332.05 1127.04,1329.72 1127.38,1327.42 1127.86,1325.53 1128.41,1324.39 1110.41,1324.39 1110.96,1325.53 1111.44,1327.42 1111.78,1329.72
  region net CLDO1: 1128.13,1330.84 1133.79,1325.18 1133.04,1323.82 1132.31,1321.5 1131.73,1318.64 1131.39,1315.71 1118.66,1328.43 1121.59,1328.77 1124.45,1329.36 1126.78,1330.09
  region net AC-LDOIN: 946.25,1545.75 956.86,1535.15 955.1,1533.21 953.55,1531.18 952.44,1529.38 951.98,1528.15 939.25,1540.87 940.49,1541.33 942.28,1542.45 944.32,1544
  region net CLDO1: 2207.32,1802.36 2201.78,1810.36 2203.66,1810.53 2205.39,1810.98 2206.72,1811.62 2207.15,1811.98 2207.38,1812.35 2212.93,1802.19 2210.85,1802.33
  region net BLDO2: 2360.16,1601.46 2366.81,1591.46 2364.82,1591.38 2363.04,1591.17 2361.76,1590.85 2361.21,1590.47 2354.56,1600.02 2355.61,1600.17 2356.95,1600.68 2358.5,1601.21
  region net AC-LDOIN: 1956,1812.35 1964,1812.35 1964.17,1810.93 1964.62,1809.35 1965.27,1807.87 1966,1806.75 1954,1806.75 1954.73,1807.87 1955.38,1809.35 1955.83,1810.93
  region net AC-LDOIN: 1945.42,1864.77 1939.76,1859.11 1938.63,1859.99 1937.2,1860.79 1935.7,1861.38 1934.39,1861.66 1942.87,1870.14 1943.14,1868.83 1943.74,1867.33 1944.53,1865.89
  region net AC-LDOIN: 1930.89,1880.53 1938.89,1880.53 1939.06,1879.11 1939.51,1877.53 1940.15,1876.05 1940.89,1874.93 1928.89,1874.93 1929.62,1876.05 1930.26,1877.53 1930.71,1879.11
  region net LINEOUTR: 1826.66,1858.63 1830.2,1862.17 1831.07,1861.71 1832.64,1861.27 1834.59,1860.9 1836.63,1860.68 1828.14,1852.19 1827.92,1854.23 1827.56,1856.19 1827.11,1857.75
  region net DDC_CEC_EN: 2144.44,1821.39 2147.98,1817.86 2147.53,1816.98 2147.08,1815.41 2146.72,1813.46 2146.49,1811.42 2138.01,1819.91 2140.05,1820.13 2142,1820.5 2143.57,1820.94
  region net DDC_CEC_EN: 2958.66,1988.96 2958.66,1993.96 2959.18,1994.1 2959.91,1994.52 2961.88,1995.99 2967.06,2000.46 2967.06,1982.46 2961.88,1986.93 2959.91,1988.4 2959.18,1988.81
  region net HSCL: 3253.66,1983.96 3253.66,1988.96 3254.18,1989.1 3254.91,1989.52 3256.88,1990.99 3262.06,1995.46 3262.06,1977.46 3256.88,1981.93 3254.91,1983.4 3254.18,1983.81
  region net HCEC: 2095.93,1820.93 2099.47,1817.39 2099.02,1816.51 2098.57,1814.95 2098.21,1812.99 2097.98,1810.96 2089.5,1819.44 2091.54,1819.66 2093.49,1820.03 2095.06,1820.47
  region net HCEC: 3202.5,2325.12 3197.5,2325.12 3197.35,2325.63 3196.94,2326.36 3195.47,2328.34 3191,2333.52 3209,2333.52 3204.53,2328.34 3203.06,2326.36 3202.65,2325.63
  region net HHPD: 3142.5,2675.12 3137.5,2675.12 3137.35,2675.63 3136.94,2676.36 3135.47,2678.34 3131,2683.52 3149,2683.52 3144.53,2678.34 3143.06,2676.36 3142.65,2675.63
  region net HSDA: 2045.89,1778.96 2045.89,1773.96 2044.95,1773.66 2043.53,1772.86 2041.89,1771.74 2040.29,1770.46 2040.29,1782.46 2041.89,1781.17 2043.53,1780.05 2044.95,1779.26
  region net HSDA: 3470.22,1968.14 3466.68,1971.67 3466.94,1972.14 3467.16,1972.95 3467.52,1975.38 3468.02,1982.21 3480.75,1969.48 3473.93,1968.97 3471.49,1968.62 3470.68,1968.4
  region net USB0-DRVVBUS: 2261.33,2217.02 2255.67,2222.68 2256.42,2224.04 2257.15,2226.37 2257.74,2229.22 2258.08,2232.16 2270.8,2219.43 2267.87,2219.09 2265.01,2218.5 2262.69,2217.77
  region net LINEOUTR: 3022.56,2265.49 3019.03,2269.02 3019.39,2269.72 3019.46,2270.68 3019.03,2273.04 3018.34,2275.44 3018.02,2277.21 3030.75,2264.48 3028.98,2264.8 3026.58,2265.48 3024.22,2265.92 3023.26,2265.85
  region net CLDO1: 407.5,2415.12 392.5,2415.12 392.37,2417.73 392.03,2420.26 391.55,2422.32 391,2423.52 409,2423.52 408.45,2422.32 407.97,2420.26 407.63,2417.73
  region net CLDO2: 3147.5,1685.12 3132.5,1685.12 3132.37,1687.73 3132.03,1690.26 3131.55,1692.32 3131,1693.52 3149,1693.52 3148.45,1692.32 3147.97,1690.26 3147.63,1687.73
  region net CLDO2: 3026.25,1273.31 3036.86,1262.71 3035.1,1260.77 3033.55,1258.74 3032.44,1256.94 3031.98,1255.71 3019.25,1268.43 3020.49,1268.89 3022.28,1270.01 3024.31,1271.56
  region net BLDO2: 2733.54,1592.92 2726.46,1599.99 2726.93,1600.94 2727.39,1602.69 2727.78,1604.89 2728.02,1607.21 2740.75,1594.48 2738.43,1594.24 2736.23,1593.85 2734.49,1593.39
  region net BLDO2: 658.75,1959.6 648.14,1970.21 649.9,1972.14 651.45,1974.17 652.56,1975.97 653.02,1977.21 665.75,1964.48 664.51,1964.02 662.72,1962.9 660.68,1961.35
  region net VCC18-LPDDR3: 1906.96,655.36 1891.96,655.36 1891.71,660.88 1891.46,664.96 1907.46,664.96 1907.21,660.88
  region net VCC18-LPDDR3: 1891.96,674.56 1906.96,674.56 1907.21,669.04 1907.46,664.96 1891.46,664.96 1891.71,669.04
  region net VCC18-LPDDR3: 2402.5,621.86 2387.5,621.86 2387.25,627.38 2387,631.46 2403,631.46 2402.75,627.38
  region net VCC18-LPDDR3: 2384.47,636.33 2390.13,641.99 2391.25,641.11 2392.69,640.31 2394.19,639.71 2395.5,639.44 2387.02,630.96 2386.74,632.27 2386.15,633.77 2385.35,635.21
  region net UART0-TX: 2095.35,1873.98 2098.88,1870.44 2098.43,1869.56 2097.99,1868 2097.62,1866.04 2097.4,1864.01 2088.91,1872.49 2090.95,1872.71 2092.9,1873.08 2094.47,1873.52
  region net EPHY-SPD-LED: 1622.44,2351.66 1622.44,2355.66 1623.29,2356 1624.65,2356.91 1628.04,2359.66 1628.04,2347.66 1624.65,2350.41 1623.29,2351.31
  region net EPHY-SPD-LED: 785.14,2354.42 787.97,2351.59 787.25,2350.53 786.83,2349.2 786.65,2347.68 786.63,2346.08 786.85,2342.99 786.98,2340.71 774.25,2353.43 776.54,2353.31 779.62,2353.09 781.22,2353.1 782.74,2353.29 784.08,2353.7
  region net EPHY-LNK-LED: 1397.4,2391.96 1395.15,2387.96 1393.9,2387.73 1392.67,2387.12 1391.48,2386.24 1390.35,2385.19 1388.33,2383.04 1386.75,2381.54 1389,2399.39 1391.54,2396.66 1394.01,2394.28 1396.08,2392.6 1396.85,2392.12
  region net EPHY-LNK-LED: 1592.03,2386.59 1594.86,2389.42 1595.92,2388.7 1597.26,2388.29 1598.78,2388.1 1600.38,2388.09 1603.46,2388.31 1605.75,2388.43 1593.02,2375.71 1593.15,2377.99 1593.37,2381.08 1593.35,2382.68 1593.17,2384.2 1592.75,2385.53
  region net $2N15: 1306,2502.79 1314,2502.79 1314.43,2501.3 1315.56,2499.15 1317.16,2496.71 1319,2494.39 1301,2494.39 1302.84,2496.71 1304.44,2499.15 1305.57,2501.3
  region net AC-LDOIN: 1921.28,2072.08 1915.62,2077.73 1916.37,2079.09 1917.09,2081.42 1917.68,2084.27 1918.02,2087.21 1930.75,2074.48 1927.82,2074.14 1924.96,2073.55 1922.63,2072.83
  region net AC-LDOIN: 713.72,1993.34 694.7,1991.15 693.84,1992.24 693.2,1993.51 692.37,1996.25 691.77,1998.79 691.43,1999.79 691,2000.52 708.84,2000.35 708.77,1999.98 708.95,1999.4 709.96,1997.71 711.63,1995.59
  region net CLDO2: 1296.34,1395.46 1296.34,1387.46 1294.85,1387.03 1292.69,1385.89 1290.25,1384.29 1287.94,1382.46 1287.94,1400.46 1290.25,1398.62 1292.69,1397.02 1294.85,1395.89
  region net VCC18-RTC: 2561.34,1488.96 2561.34,1473.96 2558.73,1473.83 2556.2,1473.49 2554.14,1473.01 2552.94,1472.46 2552.94,1490.46 2554.14,1489.91 2556.2,1489.43 2558.73,1489.09
  region net VCC18-RTC: 3091.86,1905.21 3081.25,1894.6 3079.31,1896.35 3077.28,1897.9 3075.49,1899.02 3074.25,1899.48 3086.98,1912.21 3087.44,1910.97 3088.55,1909.17 3090.1,1907.14
  region net VCC18-RTC: 1232.5,2042.47 1217.5,2041.78 1217.36,2044.38 1216.98,2046.91 1216.46,2048.97 1215.85,2050.18 1233.84,2050.87 1233.35,2049.69 1232.92,2047.63 1232.61,2045.09
  region net VCC18-RTC: 1273.14,1607.71 1283.75,1618.31 1285.69,1616.56 1287.72,1615.01 1289.51,1613.89 1290.75,1613.43 1278.02,1600.71 1277.56,1601.94 1276.45,1603.74 1274.9,1605.77
  region net AP-NMI: 2273.96,2076.28 2268.96,2074.08 2268.81,2074.64 2268.37,2075.44 2266.8,2077.55 2264.58,2080.03 2262.04,2082.48 2279.9,2084.68 2278.48,2083.12 2276.5,2081.1 2275.54,2079.96 2274.73,2078.77 2274.17,2077.53
  region net VCC18-LPDDR3: 1723.85,816.44 1723.85,801.44 1721.25,801.31 1718.72,800.97 1716.65,800.49 1715.45,799.94 1715.45,817.94 1716.65,817.39 1718.72,816.91 1721.25,816.57
  region net KEYADC: 2410.89,1888.96 2410.89,1883.96 2409.95,1883.66 2408.53,1882.86 2406.89,1881.74 2405.29,1880.46 2405.29,1892.46 2406.89,1891.17 2408.53,1890.05 2409.95,1889.26
  region net KEYADC: 2729.11,1938.96 2729.11,1943.96 2730.05,1944.26 2731.47,1945.05 2733.11,1946.17 2734.71,1947.46 2734.71,1935.46 2733.11,1936.74 2731.47,1937.86 2730.05,1938.66
  region net VDD-GPUFB: 1320.89,1435.46 1320.89,1427.46 1319.47,1427.28 1317.89,1426.83 1316.41,1426.19 1315.29,1425.46 1315.29,1437.46 1316.41,1436.72 1317.89,1436.08 1319.47,1435.63
  region net VDD-GPUFB: 1025.13,1420.93 1019.47,1426.58 1020.35,1427.71 1021.15,1429.15 1021.74,1430.65 1022.02,1431.96 1030.5,1423.47 1029.19,1423.2 1027.69,1422.61 1026.25,1421.81
  region net VDD-GPUFB: 715.53,1331.58 709.87,1325.93 708.75,1326.81 707.31,1327.61 705.81,1328.2 704.5,1328.47 712.98,1336.96 713.26,1335.65 713.85,1334.15 714.65,1332.71
  region net VDD-CPUFB: 2257.21,1542.78 2257.21,1547.78 2258.15,1548.08 2259.57,1548.87 2261.21,1550 2262.81,1551.28 2262.81,1539.28 2261.21,1540.57 2259.57,1541.69 2258.15,1542.48
  region net UART0-RX: 2127.39,1876.69 2133.39,1876.69 2133.64,1875.59 2134.32,1874.11 2135.28,1872.53 2136.39,1871.09 2124.39,1871.09 2125.49,1872.53 2126.45,1874.11 2127.13,1875.59
  region net CLDO2: 1143.66,1782.46 1143.66,1790.46 1145.15,1790.89 1147.31,1792.02 1149.75,1793.62 1152.06,1795.46 1152.06,1777.46 1149.75,1779.29 1147.31,1780.89 1145.15,1782.03
  region net CLDO1: 768.66,2043.96 768.66,2048.96 769.18,2049.1 769.91,2049.52 771.88,2050.99 777.06,2055.46 777.06,2037.46 771.88,2041.93 769.91,2043.4 769.18,2043.81
  region net CLDO1: 1982.52,1728.7 1980.67,1730.1 1978.5,1730.96 1974.5,1742.37 1978.5,1752.03 1979.95,1747.14 1982.07,1742.5 1984.84,1738.21 1988.18,1734.35 1982.52,1728.7
  region net CLDO2: 1160,1790.46 1156.48,1791.55 1153.24,1793.3 1150.4,1795.65 1148.07,1798.5 1146.33,1801.76 1145.27,1805.29 1144.91,1808.96 1137.41,1785.01 1144.91,1763.96 1145.27,1767.63 1146.33,1771.15 1148.07,1774.41 1150.4,1777.27 1153.24,1779.61 1156.48,1781.37 1160,1782.46
  region net CLDO1: 745.38,2048.96 755.86,2043.96 750.76,2043.65 745.73,2042.73 740.86,2041.21 730.38,2048.65 737.88,2048.73 745.38,2048.96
